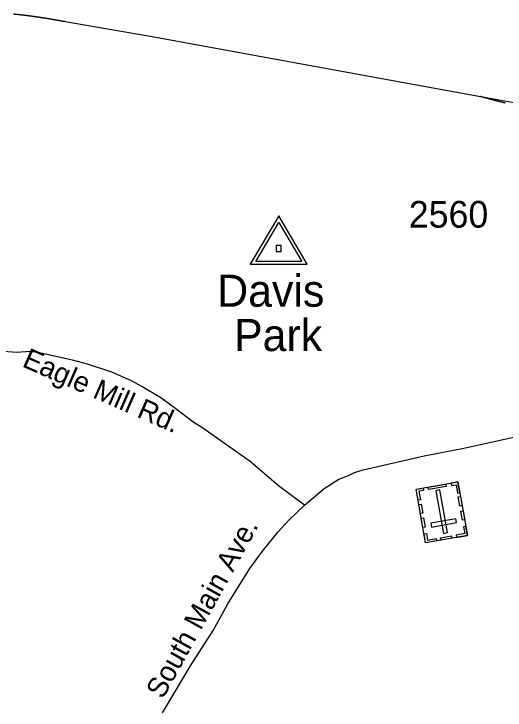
# Model space of a CAD drawing. Extents: x 1364363 to 1407445, y 538563 to 573342.
# Drawn here: x 1387829 to 1390128, y 546790 to 550046 of the extents above; entities that cross this region are included whole.
import ezdxf

# ---------------------------------------------------------------- set-up
doc = ezdxf.new("R2010")
doc.units = 0
for name, color, linetype in [('Exist Cultural Cemetery CELL', 7, 'Continuous'), ('Exist Railroad Mainline', 7, 'Continuous'), ('Exist Railroad Siding', 7, 'Continuous'), ('Exist Road Secondary Type 51 Attributed', 7, 'Continuous'), ('Exist Road Secondary Type 51 Label', 7, 'Continuous'), ('Exist Road Secondary Type 51 Number Label', 7, 'Continuous'), ('Exist Survey Geodetic Marker CELL', 7, 'Continuous'), ('Exist Survey Geodetic Marker Label', 7, 'Continuous')]:
    doc.layers.add(name, color=color, linetype=linetype)

msp = doc.modelspace()

# ---------------------------------------------------------------- linework, layer by layer
at = {"layer": 'Exist Cultural Cemetery CELL'}
for points in [[(1389952, 547606.5), (1389756, 547571.5), (1389711.2, 547822.2), (1389907.2, 547857.2)], [(1389852.7, 547835.8), (1389769.1, 547820.9), (1389767.1, 547832.1), (1389850.7, 547847)], [(1389874.7, 547851.3), (1389876.7, 547840), (1389898.3, 547843.9), (1389905.4, 547804.1), (1389916.4, 547806.1), (1389907.3, 547857.2)], [(1389743.8, 547828), (1389745.9, 547816.7), (1389724.2, 547812.9), (1389731.3, 547773.1), (1389720.4, 547771.1), (1389711.2, 547822.2)], [(1389839.5, 547616.2), (1389857.9, 547619.5), (1389822.2, 547819.1), (1389803.9, 547815.8)], [(1389919.5, 547788.4), (1389927.2, 547745.7), (1389916, 547743.7), (1389908.3, 547786.4)], [(1389735.1, 547753.1), (1389742.7, 547710.4), (1389731.5, 547708.4), (1389723.9, 547751.1)], [(1389931.3, 547722.2), (1389939, 547679.5), (1389927.8, 547677.5), (1389920.1, 547720.2)], [(1389746.7, 547688.2), (1389754.3, 547645.5), (1389743.1, 547643.5), (1389735.5, 547686.2)], [(1389899.8, 547666.4), (1389896.6, 547684.7), (1389780.6, 547664.1), (1389783.9, 547645.7)], [(1389944.4, 547649.2), (1389933.2, 547647.2), (1389938.9, 547615.5), (1389898.9, 547608.4), (1389900.9, 547597.4), (1389952, 547606.5)], [(1389748.3, 547614.2), (1389759.5, 547616.2), (1389765.1, 547584.5), (1389805.1, 547591.7), (1389807, 547580.7), (1389755.9, 547571.6)], [(1389879.1, 547593.5), (1389828, 547584.4), (1389826, 547595.6), (1389877.1, 547604.8)]]:
    msp.add_lwpolyline(points, close=True, dxfattribs=at)
at = {"layer": 'Exist Railroad Mainline'}
for points in [[(1387828, 550045.6), (1387829.4, 550045.5), (1387830.8, 550045.4), (1387832.3, 550045.2), (1387833.6, 550045.1), (1387835.2, 550044.9), (1387836.5, 550044.8), (1387838, 550044.7), (1387839.4, 550044.6), (1387840.8, 550044.4), (1387842.2, 550044.3), (1387843.7, 550044.1), (1387845.1, 550044), (1387846.5, 550043.8), (1387848, 550043.7), (1387849.4, 550043.6), (1387850.7, 550043.4), (1387852.3, 550043.2), (1387853.6, 550043), (1387855.1, 550042.9), (1387856.5, 550042.7), (1387857.9, 550042.6), (1387859.3, 550042.4), (1387860.8, 550042.3), (1387862.2, 550042.1), (1387863.7, 550042), (1387865, 550041.8), (1387866.5, 550041.7), (1387867.9, 550041.5), (1387869.4, 550041.4), (1387870.7, 550041.2), (1387872.2, 550041), (1387873.6, 550040.9), (1387875, 550040.7), (1387876.5, 550040.5), (1387877.9, 550040.3), (1387879.2, 550040.2), (1387880.8, 550040), (1387882.1, 550039.8), (1387883.6, 550039.6), (1387885, 550039.5), (1387886.4, 550039.3), (1387887.8, 550039.1), (1387889.3, 550038.9), (1387890.6, 550038.7), (1387892.2, 550038.6), (1387893.5, 550038.4), (1387895, 550038.2), (1387896.4, 550038), (1387897.8, 550037.8), (1387899.2, 550037.6), (1387900.7, 550037.4), (1387902, 550037.2), (1387903.5, 550037), (1387904.9, 550036.9), (1387906.4, 550036.7), (1387907.7, 550036.5)], [(1387907.7, 550036.5), (1387909.4, 550036.3), (1387911, 550036.1), (1387912.7, 550035.8), (1387914.3, 550035.6), (1387915.8, 550035.4), (1387917.5, 550035.1), (1387919.1, 550034.9), (1387920.8, 550034.7), (1387922.4, 550034.4), (1387924, 550034.2), (1387925.6, 550033.9), (1387927.2, 550033.8), (1387928.9, 550033.5), (1387930.6, 550033.2), (1387932.2, 550033), (1387933.9, 550032.7), (1387935.5, 550032.6), (1387937.2, 550032.3), (1387938.7, 550032.1), (1387940.3, 550031.8), (1387942, 550031.6), (1387943.6, 550031.3), (1387945.3, 550031), (1387946.9, 550030.8), (1387948.5, 550030.6), (1387950.1, 550030.4), (1387951.7, 550030.1), (1387953.4, 550029.9), (1387955, 550029.6), (1387956.6, 550029.4), (1387958.3, 550029.1), (1387959.9, 550028.9), (1387961.5, 550028.6), (1387963.1, 550028.4), (1387964.7, 550028.1), (1387966.4, 550027.9), (1387968, 550027.6), (1387969.7, 550027.3), (1387971.2, 550027), (1387972.8, 550026.8), (1387974.5, 550026.6), (1387976.1, 550026.3), (1387977.8, 550026.1), (1387979.4, 550025.8), (1387981, 550025.6), (1387982.6, 550025.2), (1387984.2, 550025), (1387985.9, 550024.7), (1387987.5, 550024.5), (1387989.1, 550024.3), (1387990.8, 550023.9), (1387992.4, 550023.7), (1387994, 550023.5), (1387995.6, 550023.2), (1387997.2, 550022.9), (1387998.9, 550022.6), (1388000.5, 550022.4), (1388002.2, 550022.1), (1388003.7, 550021.8), (1388005.3, 550021.6), (1388007, 550021.3), (1388008.6, 550021), (1388010.3, 550020.7), (1388011.9, 550020.4), (1388013.5, 550020.2), (1388015.1, 550019.9), (1388016.7, 550019.6), (1388018.4, 550019.4), (1388020, 550019), (1388021.6, 550018.8), (1388023.3, 550018.5), (1388024.8, 550018.2), (1388026.5, 550017.9), (1388028.1, 550017.7), (1388029.7, 550017.4), (1388031.4, 550017.1), (1388033, 550016.8), (1388034.7, 550016.6), (1388036.2, 550016.2), (1388037.8, 550016), (1388039.5, 550015.7), (1388041.1, 550015.4), (1388042.8, 550015.2), (1388044.4, 550014.8), (1388046, 550014.6), (1388047.6, 550014.2), (1388049.2, 550013.9), (1388050.9, 550013.7), (1388052.5, 550013.4), (1388054.1, 550013), (1388055.8, 550012.8), (1388057.3, 550012.5), (1388059, 550012.2), (1388060.6, 550011.9), (1388062.2, 550011.6), (1388063.9, 550011.3), (1388065.5, 550011), (1388067.2, 550010.7), (1388068.7, 550010.4)], [(1388068.7, 550010.4), (1388475.7, 549940), (1388952.8, 549852.4), (1389799.2, 549698.9), (1390012.4, 549659.5)], [(1390128.2, 549628.7), (1390126.9, 549629), (1390125.4, 549629.4), (1390124, 549629.7), (1390122.5, 549630.1), (1390121.2, 549630.4), (1390119.6, 549630.7), (1390118.2, 549631.1), (1390116.8, 549631.4), (1390115.3, 549631.8), (1390113.9, 549632.2), (1390112.5, 549632.5), (1390111, 549632.9), (1390109.6, 549633.2), (1390108.2, 549633.6), (1390106.7, 549634), (1390105.3, 549634.3), (1390103.8, 549634.7), (1390102.4, 549635.1), (1390101, 549635.4), (1390099.5, 549635.8), (1390098.1, 549636.1), (1390096.7, 549636.5), (1390095.2, 549636.9), (1390093.8, 549637.2), (1390092.4, 549637.5), (1390090.8, 549638), (1390089.5, 549638.3), (1390088, 549638.7), (1390086.6, 549639.1), (1390085.3, 549639.4), (1390083.8, 549639.8), (1390082.4, 549640.2), (1390080.9, 549640.6), (1390079.5, 549640.9), (1390078, 549641.3), (1390076.6, 549641.7), (1390075.1, 549642.1), (1390073.7, 549642.4), (1390072.3, 549642.8), (1390070.8, 549643.2), (1390069.5, 549643.5), (1390068, 549644), (1390066.6, 549644.3), (1390065.1, 549644.8), (1390063.8, 549645.1), (1390062.2, 549645.5), (1390060.9, 549645.9), (1390059.5, 549646.3), (1390058, 549646.6), (1390056.6, 549647.1), (1390055.1, 549647.4), (1390053.7, 549647.8), (1390052.3, 549648.2), (1390050.8, 549648.6), (1390049.5, 549649), (1390048, 549649.4), (1390046.6, 549649.7), (1390045.1, 549650.2), (1390043.8, 549650.6), (1390042.3, 549650.9), (1390040.9, 549651.4), (1390039.5, 549651.7), (1390038, 549652.2), (1390036.6, 549652.6), (1390035.3, 549652.9), (1390033.7, 549653.4), (1390032.4, 549653.7), (1390030.8, 549654.2), (1390029.5, 549654.6), (1390028.1, 549655), (1390026.6, 549655.4), (1390025.2, 549655.7), (1390023.8, 549656.2), (1390022.3, 549656.6), (1390021, 549657), (1390019.5, 549657.4), (1390018.1, 549657.8), (1390016.7, 549658.3), (1390015.3, 549658.6), (1390013.8, 549659.1), (1390012.4, 549659.5)]]:
    msp.add_lwpolyline(points, dxfattribs=at)
at = {"layer": 'Exist Railroad Siding'}
msp.add_lwpolyline([(1390012.4, 549659.5), (1390204.4, 549624.5), (1390699, 549533.9), (1390792.1, 549517.7)], dxfattribs=at)
at = {"layer": 'Exist Road Secondary Type 51 Attributed'}
for points in [[(1389188.8, 547747.4), (1389067.6, 547839.2), (1388935.5, 547952.8), (1388713.8, 548108.1), (1388666.6, 548138.2), (1388580.7, 548202.6), (1388516.3, 548249.9), (1388428.3, 548303.6), (1388378.9, 548329.4), (1388286.8, 548369.8), (1388173.3, 548406.9), (1388103.8, 548425.5), (1387941.7, 548462.6), (1387905, 548466.3), (1387842.8, 548462.6), (1387780.5, 548466.3)], [(1389188.8, 547747.4), (1389280.7, 547825.3), (1389350.2, 547869.3), (1389395.1, 547886.8), (1389423.4, 547900.4), (1389463.7, 547913.4), (1389748.7, 547978.3), (1389927.1, 548013), (1390352.2, 548107.2), (1390445.5, 548134.1)], [(1388524.9, 546776.6), (1388591.5, 546888.3), (1388656.1, 546996.4), (1388761.1, 547161.8), (1388829.8, 547286.4), (1388932.8, 547451.8), (1388992.6, 547533.4), (1389065.3, 547623.6), (1389113.9, 547676.9), (1389188.8, 547747.4)]]:
    msp.add_lwpolyline(points, dxfattribs=at)
at = {"layer": 'Exist Survey Geodetic Marker CELL'}
for points in [[(1389202.2, 548875.4), (1389068.2, 549101.4), (1388934.7, 548875.4)], [(1389176.3, 548887.5), (1388960.7, 548887.5), (1389068.2, 549069.6)], [(1389080.5, 548934.1), (1389080.5, 548962.3), (1389056.3, 548962.3), (1389056.3, 548934.1)]]:
    msp.add_lwpolyline(points, close=True, dxfattribs=at)

# ---------------------------------------------------------------- texts
at = {"layer": 'Exist Road Secondary Type 51 Label'}
for s, rotation, p in [('Eagle Mill Rd.', 336.2982, (1387863.3, 548398.3)), ('South Main Ave.', 61.1298, (1388525.9, 546837.1))]:
    msp.add_text(s, height=95, rotation=rotation, dxfattribs=at).set_placement(p)
at = {"layer": 'Exist Road Secondary Type 51 Number Label'}
msp.add_text('2560', height=125, dxfattribs=at).set_placement((1389677.2, 549045.9))
at = {"layer": 'Exist Survey Geodetic Marker Label'}
for s, p in [('Davis', (1388780.6, 548676.1)), ('Park', (1388859.4, 548468.7))]:
    msp.add_text(s, height=150, dxfattribs=at).set_placement(p)

doc.saveas('drawing.dxf')
